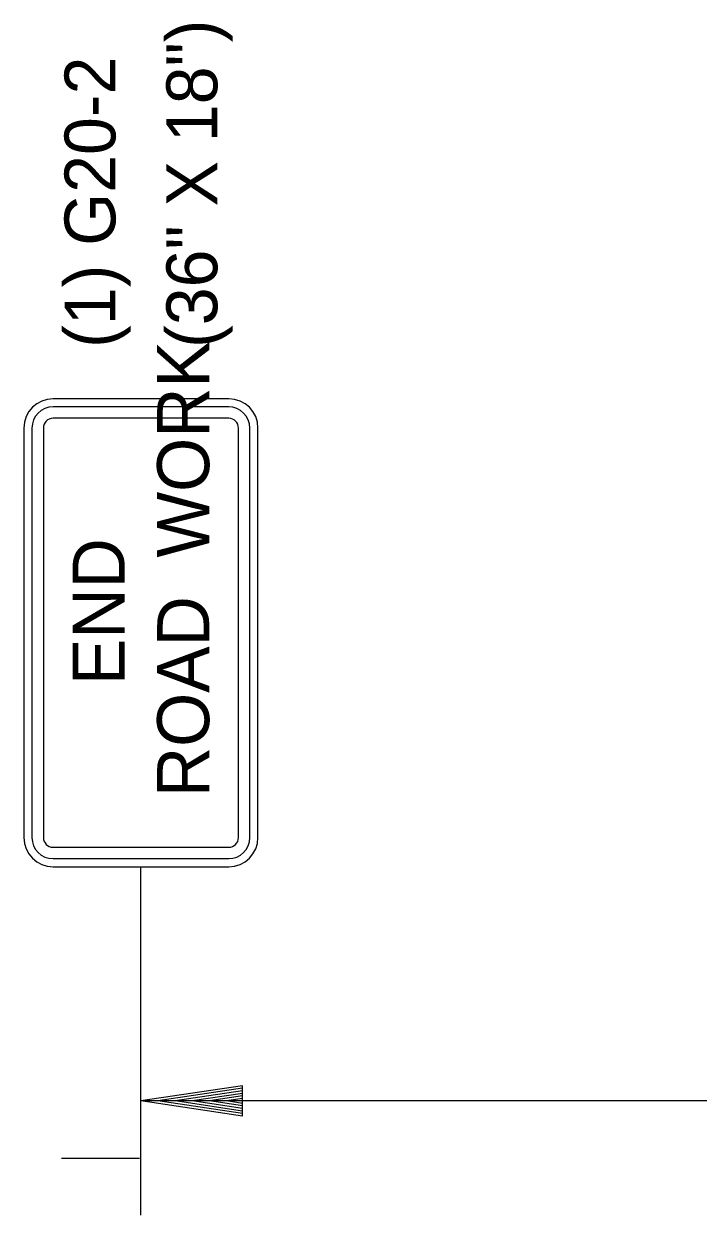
# Model space of a CAD drawing. Extents: x 913 to 1207, y 319 to 519.
# Drawn here: x 997.66 to 1013.55, y 430.66 to 458.75 of the extents above; entities that cross this region are included whole.
import ezdxf

# ---------------------------------------------------------------- set-up
doc = ezdxf.new("R2010")
doc.units = 0
doc.layers.add('R_Annotation', color=7, linetype='Continuous')
doc.layers.add('R_Draft', color=7, linetype='Continuous')

msp = doc.modelspace()

# ---------------------------------------------------------------- linework, layer by layer
at = {"layer": 'R_Annotation'}
for p, q in [((1002.485, 449.907), (998.347, 449.907)), ((1002.485, 449.716), (998.347, 449.716)), ((997.657, 449.217), (997.657, 439.561)), ((997.849, 449.217), (997.849, 439.561)), ((998.117, 449.217), (998.117, 439.561)), ((1002.485, 449.447), (998.347, 449.447)), ((1002.715, 439.561), (1002.715, 449.217)), ((1002.983, 439.561), (1002.983, 449.217)), ((1003.175, 439.561), (1003.175, 449.217)), ((998.347, 439.331), (1002.485, 439.331)), ((998.347, 439.063), (1002.485, 439.063)), ((998.347, 438.871), (1002.485, 438.871))]:
    msp.add_line(p, q, dxfattribs=at)
for centre, radius, start, end in [((998.347, 449.217), 0.69, 90, 180), ((1002.485, 449.217), 0.69, 360, 90), ((998.347, 449.217), 0.498, 90, 180), ((1002.485, 449.217), 0.498, 360, 90), ((998.347, 449.217), 0.23, 90, 180), ((1002.485, 449.217), 0.23, 360, 90), ((998.347, 439.561), 0.69, 180, 270), ((998.347, 439.561), 0.498, 180, 270), ((998.347, 439.561), 0.23, 180, 270), ((1002.485, 439.561), 0.498, 270, 360), ((1002.485, 439.561), 0.23, 270, 360), ((1002.485, 439.561), 0.69, 270, 360)]:
    msp.add_arc(centre, radius, start, end, dxfattribs=at)
at = {"layer": 'R_Draft'}
for p, q in [((1000.416, 433.35), (1000.416, 438.871)), ((1002.81, 433.709), (1000.416, 433.35)), ((1002.81, 433.649), (1000.816, 433.35)), ((1002.81, 433.589), (1001.227, 433.35)), ((1002.81, 433.529), (1001.625, 433.35)), ((1002.81, 433.467), (1002.032, 433.35)), ((1002.81, 432.991), (1002.81, 433.709)), ((1034.123, 433.35), (1000.416, 433.35)), ((1002.81, 432.991), (1000.416, 433.35)), ((1000.418, 430.657), (1000.418, 433.35)), ((1002.81, 433.051), (1000.816, 433.35)), ((1002.81, 433.112), (1001.227, 433.35)), ((1002.81, 433.171), (1001.625, 433.35)), ((1002.81, 433.234), (1002.032, 433.35)), ((1002.81, 433.406), (1002.432, 433.35)), ((1002.81, 433.294), (1002.432, 433.35)), ((1000.379, 431.997), (998.541, 431.997))]:
    msp.add_line(p, q, dxfattribs=at)

# ---------------------------------------------------------------- texts
at = {"layer": 'R_Annotation'}
for s, height, p in [('(36" X 18")', 1.2, (1002.216, 451.107)), ('(1) G20-2', 1.2, (999.816, 451.107)), ('ROAD  WORK', 1.2262, (1002.025, 440.515)), ('END', 1.2262, (1000.033, 443.157))]:
    msp.add_text(s, height=height, rotation=90, dxfattribs=at).set_placement(p)

doc.saveas('drawing.dxf')
